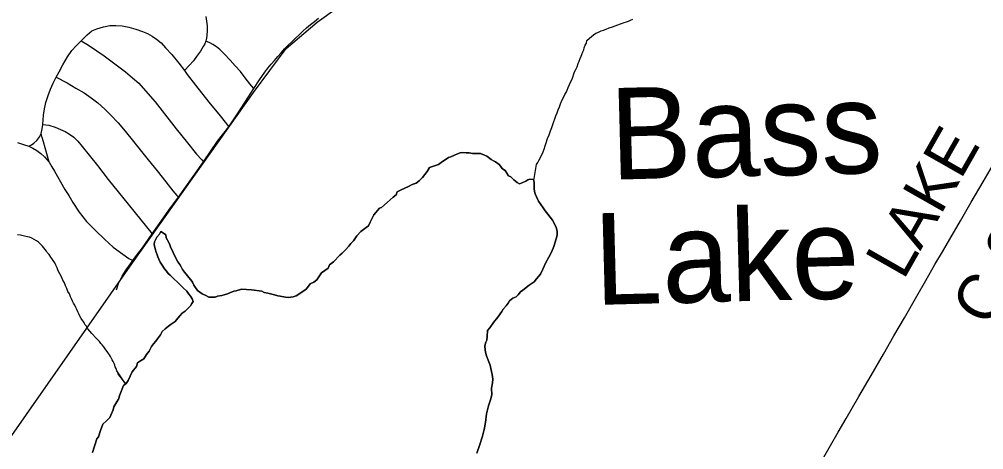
# Model space of a CAD drawing. Extents: x 103424 to 286016, y 38711 to 110967.
# Drawn here: x 137459 to 143819, y 88820 to 91660 of the extents above; entities that cross this region are included whole.
import ezdxf

# ---------------------------------------------------------------- set-up
doc = ezdxf.new("R2010")
doc.units = 0
for name, color, linetype in [('GM_X_County_Road', 7, 'Continuous'), ('GM_X_County_Road_Text', 7, 'Continuous'), ('GM_X_Major_Lake', 7, 'Continuous'), ('GM_X_Major_Lake_Text', 7, 'Continuous'), ('GM_X_Major_River', 7, 'Continuous'), ('GM_X_Minor_River', 7, 'Continuous'), ('GM_X_Rail_Line', 7, 'Continuous'), ('GM_X_Township_Road', 7, 'Continuous')]:
    doc.layers.add(name, color=color, linetype=linetype)

msp = doc.modelspace()

# ---------------------------------------------------------------- linework, layer by layer
at = {"layer": 'GM_X_County_Road'}
msp.add_lwpolyline([(142737.7, 88724.3), (142807.8, 88846.7), (142859.4, 88936.8), (142911.1, 89026.8), (142953.3, 89098.9), (142995.6, 89171), (143076.2, 89310.7), (143156.8, 89450.4), (143226.2, 89570.8), (143295.6, 89691.2), (143378, 89834.2), (143437.6, 89937.6), (143497.2, 90041.1), (143546, 90125), (143594.7, 90209), (143665.5, 90331), (143736.2, 90452.9), (143814.2, 90586.8), (143892.1, 90720.6)], dxfattribs=at)
at = {"layer": 'GM_X_Major_Lake'}
for points in [[(140541.7, 90756), (140527.6, 90764), (140499.3, 90773.9), (140463.1, 90773.7), (140446.9, 90775.6), (140424.7, 90779.6), (140406.6, 90779.5), (140384.4, 90781.4), (140366.3, 90779.2), (140348.2, 90773.1), (140328.1, 90762.9), (140303.9, 90752.7), (140289.8, 90748.6), (140241.6, 90716), (140223.5, 90701.8), (140163.1, 90681.3), (140149.1, 90654.9), (140117, 90616.4), (140097, 90594.1), (140076.9, 90579.9), (140048.7, 90569.6), (140026.6, 90557.4), (139976.3, 90534.9), (139950.1, 90520.7), (139944.2, 90502.5), (139924.1, 90486.2), (139885.9, 90451.7), (139847.8, 90419.2), (139833.7, 90413.1), (139797.6, 90370.5), (139773.6, 90321.9), (139761.6, 90297.6), (139745.5, 90285.4), (139711.3, 90261), (139685.3, 90230.6), (139663.2, 90198.2), (139645.1, 90179.9), (139631.1, 90163.7), (139611, 90139.4), (139589, 90117.1), (139572.9, 90102.9), (139530.7, 90060.3), (139504.6, 90039.9), (139496.7, 90017.7), (139452.4, 89987.2), (139420.4, 89940.6), (139400.3, 89926.3), (139376.1, 89914.1), (139352.1, 89881.7), (139336, 89869.5), (139285.8, 89834.9), (139265.6, 89828.7), (139249.5, 89826.6), (139231.4, 89824.5), (139215.3, 89826.4), (139178.9, 89834.3), (139164.8, 89836.3), (139142.6, 89842.2), (139098.3, 89852), (139074, 89858), (139057.9, 89866), (138991.3, 89875.7), (138924.8, 89879.4), (138888.6, 89869.1), (138874.5, 89867), (138848.3, 89854.7), (138832.2, 89848.6), (138810.1, 89842.4), (138794, 89838.3), (138765.8, 89834.1), (138751.7, 89825.9), (138729.5, 89825.8), (138709.4, 89827.7), (138689.2, 89837.7), (138664.9, 89849.7), (138634.6, 89871.7), (138610.3, 89905.9), (138602.2, 89926), (138590, 89940.1), (138577.9, 89956.2), (138559.7, 89978.3), (138549.5, 89992.3), (138535.3, 90008.4), (138527.2, 90026.5), (138517.1, 90042.6), (138504.9, 90060.7), (138496.8, 90074.8), (138488.7, 90090.9), (138478.5, 90111), (138468.3, 90133.1), (138458.2, 90151.3), (138452.1, 90171.4), (138446, 90187.5), (138435.8, 90203.6), (138427.7, 90217.7), (138425.6, 90237.9), (138409.4, 90249.9), (138393.3, 90259.9), (138383.3, 90241.7), (138365.2, 90223.4), (138359.2, 90209.2)], [(140851.3, 90597.5), (140844.7, 90602.2), (140826.5, 90606.2), (140812.4, 90600.1), (140798.3, 90591.9), (140780.2, 90583.7), (140758.1, 90573.5), (140741.9, 90583.5), (140719.7, 90601.6), (140701.5, 90619.6), (140685.3, 90627.6), (140663, 90661.8), (140644.8, 90673.8), (140622.6, 90701.9), (140600.3, 90720), (140586.2, 90725.9), (140570, 90736), (140541.7, 90756)], [(140476.9, 88798.1), (140492.8, 88848.6), (140512.7, 88909.3), (140524.7, 88953.7), (140532.5, 89000.2), (140540.4, 89056.7), (140552.3, 89109.3), (140566.2, 89149.7), (140574.1, 89182.1), (140574, 89226.4), (140579.9, 89260.8), (140581.8, 89285), (140577.6, 89315.3), (140569.4, 89355.6), (140563.3, 89377.7), (140555.1, 89399.9), (140538.9, 89440.2), (140534.8, 89454.3), (140530.7, 89476.4), (140528.5, 89504.7), (140534.5, 89528.9), (140542.5, 89543.1), (140544.4, 89567.3), (140546.3, 89605.7), (140562.3, 89623.9), (140586.4, 89658.4), (140614.4, 89694.9), (140640.5, 89731.3), (140650.5, 89747.5), (140670.6, 89769.8), (140682.6, 89788.1), (140690.6, 89802.2), (140712.7, 89820.5), (140734.8, 89828.7), (140748.9, 89842.9), (140764.9, 89861.2), (140779, 89873.3), (140821.2, 89905.9), (140853.3, 89928.2), (140869.4, 89948.5), (140895.5, 89978.9), (140911.5, 90011.3), (140931.5, 90055.8), (140951.5, 90090.2), (140969.5, 90122.6), (140983.4, 90161), (140999.4, 90211.6), (141005.3, 90235.8), (141005.2, 90262.1), (140999.1, 90286.2), (140986.9, 90314.4), (140974.7, 90334.5), (140944.3, 90374.7), (140926.1, 90396.8), (140913.9, 90416.9), (140897.7, 90439.1), (140883.5, 90461.2), (140869.3, 90489.4), (140861.1, 90507.5), (140857, 90523.6), (140854.9, 90543.8), (140854.8, 90582.1), (140851.3, 90597.5)], [(138359.2, 90209.2), (138351.2, 90191), (138349.3, 90174.9), (138355.4, 90144.6), (138361.6, 90122.5), (138367.7, 90106.4), (138371.8, 90092.3), (138379.9, 90078.2), (138388, 90058), (138400.2, 90037.9), (138416.4, 90013.8), (138430.6, 89997.7), (138440.7, 89983.7), (138454.9, 89971.6), (138477.1, 89947.5), (138501.4, 89925.5), (138539.9, 89887.3), (138564.1, 89865.3), (138576.3, 89847.2), (138588.4, 89833.1), (138598.6, 89815), (138604.7, 89798.9), (138596.7, 89784.7), (138588.7, 89768.5), (138574.6, 89756.3), (138552.6, 89734), (138532.4, 89721.8), (138518.4, 89703.6), (138504.4, 89687.4), (138486.3, 89667.1), (138460.2, 89648.8), (138442.1, 89634.5), (138422, 89618.3), (138401.9, 89600), (138389.9, 89577.8), (138369.9, 89551.4), (138359.8, 89537.2), (138343.8, 89519), (138329.8, 89500.7), (138315.8, 89470.4), (138297.7, 89448.1), (138279.7, 89419.7), (138257.6, 89405.5), (138237.5, 89393.3), (138231.5, 89369), (138203.4, 89334.6), (138177.5, 89275.9), (138163.4, 89257.6), (138145.4, 89243.4), (138121.4, 89182.8), (138113.5, 89154.5), (138101.4, 89136.2), (138083.4, 89103.8), (138077.5, 89083.6), (138063.5, 89047.2), (138055.5, 89033.1), (138033.4, 89010.7), (138009.3, 88988.4), (137995.4, 88946), (137981.4, 88905.5), (137969.4, 88891.3), (137941.5, 88802.4)]]:
    msp.add_lwpolyline(points, dxfattribs=at)
at = {"layer": 'GM_X_Major_River'}
for points in [[(140851.3, 90597.5), (140869.9, 90702.3), (140877.8, 90714.6), (140885.6, 90728.9), (140893.4, 90743.2), (140901.2, 90759.5), (140909, 90773.7), (140912.8, 90785.9), (140920.6, 90804.3), (140926.2, 90824.6), (140933.9, 90844.9), (140941.5, 90873.3), (140953.2, 90897.8), (140962.8, 90924.2), (140970.5, 90946.6), (140978.2, 90966.9), (140983.9, 90985.2), (140991.6, 91003.5), (140997.3, 91023.9), (141005.1, 91042.2), (141012.8, 91062.5), (141020.5, 91082.9), (141028.2, 91103.2), (141039.8, 91129.7), (141049.6, 91148), (141057.4, 91164.3), (141065.2, 91176.6), (141071, 91192.9), (141078.7, 91211.2), (141086.5, 91229.5), (141096.2, 91249.9), (141104, 91266.2), (141121.3, 91313), (141129.1, 91329.3), (141136.8, 91347.6), (141144.5, 91367.9), (141150.3, 91384.2), (141158, 91402.5), (141163.8, 91416.8), (141169.6, 91429), (141175.4, 91445.3), (141181.2, 91459.5), (141185, 91471.7), (141190.7, 91490), (141198.6, 91502.3), (141202.3, 91520.5), (141218.2, 91534.9), (141232.1, 91547.3), (141246, 91557.7), (141262, 91568.1), (141274, 91572.3), (141296, 91584.8), (141312.1, 91589.2), (141328.1, 91595.5), (141348.1, 91604), (141370.2, 91610.4), (141388.2, 91616.8), (141406.3, 91623.2), (141424.3, 91629.6), (141436.4, 91633.8), (141448.4, 91638.1), (141462.4, 91644.4), (141476.5, 91648.7), (141490.5, 91655), (141504.5, 91661.3)], [(138359.2, 90209.2), (138365.2, 90223.4), (138383.3, 90241.7), (138393.3, 90259.9), (138409.4, 90249.9), (138425.6, 90237.9), (138427.7, 90217.7), (138435.8, 90203.6), (138446, 90187.5), (138452.1, 90171.4), (138458.2, 90151.3), (138468.3, 90133.1), (138478.5, 90111), (138488.7, 90090.9), (138496.8, 90074.8), (138504.9, 90060.7), (138517.1, 90042.6), (138527.2, 90026.5), (138535.3, 90008.4), (138549.5, 89992.3), (138559.7, 89978.3), (138577.9, 89956.2), (138590, 89940.1), (138602.2, 89926), (138610.3, 89905.9), (138634.6, 89871.7), (138664.9, 89849.7), (138689.2, 89837.7), (138709.4, 89827.7), (138729.5, 89825.8), (138751.7, 89825.9), (138765.8, 89834.1), (138794, 89838.3), (138810.1, 89842.4), (138832.2, 89848.6), (138848.3, 89854.7), (138874.5, 89867), (138888.6, 89869.1), (138924.8, 89879.4), (138991.3, 89875.7), (139057.9, 89866), (139074, 89858), (139098.3, 89852), (139142.6, 89842.2), (139164.8, 89836.3), (139178.9, 89834.3), (139215.3, 89826.4), (139231.4, 89824.5), (139249.5, 89826.6), (139265.6, 89828.7), (139285.8, 89834.9), (139336, 89869.5), (139352.1, 89881.7), (139376.1, 89914.1), (139400.3, 89926.3), (139420.4, 89940.6), (139452.4, 89987.2), (139496.7, 90017.7), (139504.6, 90039.9), (139530.7, 90060.3), (139572.9, 90102.9), (139589, 90117.1), (139611, 90139.4), (139631.1, 90163.7), (139645.1, 90179.9), (139663.2, 90198.2), (139685.3, 90230.6), (139711.3, 90261), (139745.5, 90285.4), (139761.6, 90297.6), (139773.6, 90321.9), (139797.6, 90370.5), (139833.7, 90413.1), (139847.8, 90419.2), (139885.9, 90451.7), (139924.1, 90486.2), (139944.2, 90502.5), (139950.1, 90520.7), (139976.3, 90534.9), (140026.6, 90557.4), (140048.7, 90569.6), (140076.9, 90579.9), (140097, 90594.1), (140117, 90616.4), (140149.1, 90654.9), (140163.1, 90681.3), (140223.5, 90701.8), (140241.6, 90716), (140289.8, 90748.6), (140303.9, 90752.7), (140328.1, 90762.9), (140348.2, 90773.1), (140366.3, 90779.2), (140384.4, 90781.4), (140406.6, 90779.5), (140424.7, 90779.6), (140446.9, 90775.6), (140463.1, 90773.7), (140499.3, 90773.9), (140527.6, 90764), (140541.7, 90756)], [(140541.7, 90756), (140570, 90736), (140586.2, 90725.9), (140600.3, 90720), (140622.6, 90701.9), (140644.8, 90673.8), (140663, 90661.8), (140685.3, 90627.6), (140701.5, 90619.6), (140719.7, 90601.6), (140741.9, 90583.5), (140758.1, 90573.5), (140780.2, 90583.7), (140798.3, 90591.9), (140812.4, 90600.1), (140826.5, 90606.2), (140844.7, 90602.2), (140851.3, 90597.5)], [(140851.3, 90597.5), (140854.8, 90582.1), (140854.9, 90543.8), (140857, 90523.6), (140861.1, 90507.5), (140869.3, 90489.4), (140883.5, 90461.2), (140897.7, 90439.1), (140913.9, 90416.9), (140926.1, 90396.8), (140944.3, 90374.7), (140974.7, 90334.5), (140986.9, 90314.4), (140999.1, 90286.2), (141005.2, 90262.1), (141005.3, 90235.8), (140999.4, 90211.6), (140983.4, 90161), (140969.5, 90122.6), (140951.5, 90090.2), (140931.5, 90055.8), (140911.5, 90011.3), (140895.5, 89978.9), (140869.4, 89948.5), (140853.3, 89928.2), (140821.2, 89905.9), (140779, 89873.3), (140764.9, 89861.2), (140748.9, 89842.9), (140734.8, 89828.7), (140712.7, 89820.5), (140690.6, 89802.2), (140682.6, 89788.1), (140670.6, 89769.8), (140650.5, 89747.5), (140640.5, 89731.3), (140614.4, 89694.9), (140586.4, 89658.4), (140562.3, 89623.9), (140546.3, 89605.7), (140544.4, 89567.3), (140542.5, 89543.1), (140534.5, 89528.9), (140528.5, 89504.7), (140530.7, 89476.4), (140534.8, 89454.3), (140538.9, 89440.2), (140555.1, 89399.9), (140563.3, 89377.7), (140569.4, 89355.6), (140577.6, 89315.3), (140581.8, 89285), (140579.9, 89260.8), (140574, 89226.4), (140574.1, 89182.1), (140566.2, 89149.7), (140552.3, 89109.3), (140540.4, 89056.7), (140532.5, 89000.2), (140524.7, 88953.7), (140512.7, 88909.3), (140492.8, 88848.6), (140476.9, 88798.1)], [(137941.5, 88802.4), (137969.4, 88891.3), (137981.4, 88905.5), (137995.4, 88946), (138009.3, 88988.4), (138033.4, 89010.7), (138055.5, 89033.1), (138063.5, 89047.2), (138077.5, 89083.6), (138083.4, 89103.8), (138101.4, 89136.2), (138113.5, 89154.5), (138121.4, 89182.8), (138145.4, 89243.4), (138163.4, 89257.6), (138177.5, 89275.9), (138203.4, 89334.6), (138231.5, 89369), (138237.5, 89393.3), (138257.6, 89405.5), (138279.7, 89419.7), (138297.7, 89448.1), (138315.8, 89470.4), (138329.8, 89500.7), (138343.8, 89519), (138359.8, 89537.2), (138369.9, 89551.4), (138389.9, 89577.8), (138401.9, 89600), (138422, 89618.3), (138442.1, 89634.5), (138460.2, 89648.8), (138486.3, 89667.1), (138504.4, 89687.4), (138518.4, 89703.6), (138532.4, 89721.8), (138552.6, 89734), (138574.6, 89756.3), (138588.7, 89768.5), (138596.7, 89784.7), (138604.7, 89798.9), (138598.6, 89815), (138588.4, 89833.1), (138576.3, 89847.2), (138564.1, 89865.3), (138539.9, 89887.3), (138501.4, 89925.5), (138477.1, 89947.5), (138454.9, 89971.6), (138440.7, 89983.7), (138430.6, 89997.7), (138416.4, 90013.8), (138400.2, 90037.9), (138388, 90058), (138379.9, 90078.2), (138371.8, 90092.3), (138367.7, 90106.4), (138361.6, 90122.5), (138355.4, 90144.6), (138349.3, 90174.9), (138351.2, 90191), (138359.2, 90209.2)]]:
    msp.add_lwpolyline(points, dxfattribs=at)
at = {"layer": 'GM_X_Minor_River'}
msp.add_lwpolyline([(138106, 89323.2), (138158.6, 89253.9), (138101.6, 89341.3), (138097.3, 89355.4), (138091.1, 89367.4), (138088.9, 89377.5), (138084.6, 89389.5), (138078.4, 89401.5), (138072.1, 89413.5), (138065.8, 89425.5), (138059.6, 89435.5), (138053.3, 89445.5), (138047.1, 89455.5), (138038.8, 89467.5), (138030.5, 89479.5), (138016.1, 89499.4), (138005.8, 89511.3), (137997.5, 89521.3), (137987.2, 89533.2), (137976.9, 89545.2), (137966.6, 89557.1), (137937.8, 89586.9), (137923.4, 89602.8), (137911, 89618.7), (137900.6, 89636.7), (137892.3, 89646.7), (137886.1, 89658.7), (137877.8, 89670.7), (137867.4, 89686.6), (137859.1, 89700.6), (137850.7, 89716.6), (137844.4, 89730.7), (137838.1, 89744.7), (137831.8, 89758.7), (137825.5, 89772.8), (137817.2, 89786.8), (137808.9, 89800.7), (137802.6, 89814.8), (137796.3, 89828.8), (137789.8, 89848.9), (137779.5, 89864.9), (137773.1, 89882.9), (137764.7, 89901), (137756.3, 89921), (137745.8, 89939), (137737.4, 89961.1), (137726.9, 89981.1), (137716.5, 90001.1), (137708.1, 90019.2), (137699.7, 90037.2), (137693.3, 90053.2), (137683, 90069.2), (137674.7, 90081.2), (137666.4, 90091.1), (137656.1, 90107.1), (137643.7, 90121), (137637.5, 90131), (137629.2, 90141), (137620.9, 90153), (137612.7, 90162.9), (137598.3, 90176.8), (137586, 90188.7), (137571.7, 90198.5), (137541.1, 90216.2), (137526.9, 90222), (137512.7, 90225.8), (137494.4, 90229.5), (137468.1, 90235.1), (137447.9, 90238.7)], dxfattribs=at)
at = {"layer": 'GM_X_Rail_Line'}
msp.add_lwpolyline([(133875.3, 84761), (134206.1, 85023.5), (134695.7, 85421.3), (135168.4, 85804.7), (135472.6, 86146.8), (135770.9, 86563.5), (136107.4, 87051.7), (138204.8, 90053), (139003.6, 91176.8), (139218.1, 91468.2), (139423.2, 91640.3), (139671.2, 91822), (140345.3, 92305.3), (142112.2, 93585.6), (142557.7, 93916.9), (142922.5, 94241.9), (143182.7, 94627.5), (143325.5, 94997.6), (143391, 95277.5), (143535.3, 96306.5), (143604.3, 97220.4), (143676.2, 97697.4)], dxfattribs=at)
at = {"layer": 'GM_X_Township_Road'}
for points in [[(138208.1, 90067.8), (138232.9, 90102.1), (138272.1, 90152.9), (138336.2, 90244.4), (138410.4, 90350.7), (138445.1, 90400.2), (138508.5, 90487.4), (138557.6, 90554.7), (138606.7, 90622), (138674.2, 90719.5), (138720.6, 90788.2), (138767, 90856.9), (138839.8, 90951.2), (138897.3, 91037.2), (138946.8, 91111.4), (139006.2, 91202.5), (139043.9, 91260.2), (139078, 91310.5), (139099, 91337.4), (139119.9, 91363.5), (139141.3, 91389.3), (139163.3, 91414.7), (139185.7, 91439.8), (139208.3, 91464.4), (139231.8, 91488.6), (139255.2, 91512.4), (139279.4, 91535.8), (139303.8, 91558.8), (139328.7, 91581.4), (139353.9, 91603.5), (139379.6, 91625.2), (139405.6, 91646.3), (139431.7, 91667.1)], [(138688.6, 91678), (138694.4, 91647.4), (138697.4, 91616.8), (138698.7, 91584.5), (138696.8, 91556), (138693.6, 91535.1), (138689.2, 91514.9), (138682.2, 91498.4), (138672.5, 91479.9), (138653.7, 91450.3), (138628.7, 91414.8), (138607.3, 91386.3), (138578.7, 91355.2), (138548.9, 91323.3)], [(137521.1, 90823.1), (137539.6, 90832.1), (137555.5, 90842), (137575.4, 90861.2), (137594.7, 90887.1), (137604.2, 90907.1), (137610.8, 90938.4), (137615.1, 90966.9), (137619.8, 91027.2), (137625.8, 91068.7), (137634.9, 91111.9), (137648.8, 91156.3), (137665.4, 91198.7), (137683.5, 91239.4), (137703.2, 91277.6), (137721.1, 91314.1), (137747.2, 91360.3), (137777.2, 91413.5), (137804.6, 91453.9), (137833.1, 91485.1), (137868.2, 91518.9), (137906.7, 91556.7), (137936.5, 91583.2), (137970.9, 91598.4), (138014.7, 91611), (138056.4, 91618.3), (138096.2, 91620.3), (138138, 91616.3), (138180.4, 91608.3), (138227.4, 91595.8), (138271.9, 91579.9), (138305, 91566.6), (138335.5, 91549.4), (138363.3, 91530.1), (138393.8, 91504.3), (138424.3, 91471.8), (138464.1, 91428.1), (138510.5, 91370.4), (138548.9, 91323.3), (138566.8, 91296.8), (138620.5, 91225.2), (138709.3, 91113.2), (138782.9, 91023.8), (138839.8, 90951.2)], [(137868.2, 91518.9), (137914.6, 91489.7), (137969.6, 91451.9), (138018.7, 91418.8), (138088.9, 91367.1), (138158.9, 91314.3), (138206.3, 91275), (138248, 91237.8), (138292.4, 91188.8), (138354.7, 91115.9), (138417, 91036.3), (138494.3, 90937.7), (138568.9, 90845.4), (138628.3, 90771.2), (138663.1, 90731.8), (138674.2, 90719.5)], [(139006.2, 91202.5), (138980.3, 91234.8), (138949.3, 91275), (138917, 91314.9), (138883.5, 91352.2), (138849.9, 91390.2), (138812.6, 91430.7), (138781.6, 91461.1), (138759.4, 91478.8), (138735.4, 91493.3), (138715.2, 91504), (138689.2, 91514.9)], [(137703.2, 91277.6), (137773.7, 91241.1), (137832.8, 91206.7), (137885.9, 91175.7), (137932.7, 91141.3), (137976.9, 91108.6), (138023.8, 91067.1), (138060.9, 91030.8), (138111.2, 90976), (138158.1, 90921.3), (138212, 90853.2), (138309.2, 90733.9), (138367.5, 90660.9), (138425.9, 90588), (138470.9, 90529.2), (138497.4, 90496.8), (138508.5, 90487.4)], [(137615.1, 90966.9), (137653.6, 90960.7), (137696.1, 90948.1), (137729.9, 90933.5), (137761.7, 90918.9), (137790.9, 90902.3), (137818, 90882.4), (137844.5, 90855.9), (137873.1, 90821.6), (137920.9, 90764.3), (137974.9, 90694.9), (138045.6, 90603.6), (138111, 90522.4), (138176.4, 90441.2), (138260.7, 90338), (138336.2, 90244.4)], [(137655, 90718.2), (137629.3, 90811.5), (137618.9, 90851.1), (137610.8, 90880), (137604.2, 90907.1)], [(137447.1, 90846.8), (137486, 90833.5), (137521.1, 90823.1), (137548.2, 90810.8), (137574.3, 90794.6), (137602, 90774.4), (137625.5, 90752.4), (137655, 90718.2), (137674.4, 90687.4), (137691, 90658.1), (137730.3, 90588.4), (137758.9, 90536.8), (137785.2, 90497.2), (137812.3, 90452.4), (137854.7, 90387.6), (137903, 90326.3), (137964.3, 90263.9), (138020.9, 90209.7), (138078.6, 90156.7), (138141, 90109.5), (138182.5, 90082.6), (138208.1, 90067.8)], [(138101.1, 89875.6), (138114.3, 89916.8), (138136.6, 89965.8), (138163.6, 90006.8), (138192.5, 90046.7), (138208.1, 90067.8)]]:
    msp.add_lwpolyline(points, dxfattribs=at)

# ---------------------------------------------------------------- texts
at = {"layer": 'GM_X_County_Road_Text'}
for s, rotation, p in [('LAKE', 60.34711, (143289.2, 89933.7)), ('C-23', 60.25515, (143856.8, 89620.9))]:
    msp.add_text(s, height=301.87, rotation=rotation, dxfattribs=at).set_placement(p)
at = {"layer": 'GM_X_Major_Lake_Text'}
for s, height, rotation, p in [('Bass', 604.15, 1.49831, (141360.3, 90601.4)), ('Lake', 604.14, 1.49788, (141254.8, 89775))]:
    msp.add_text(s, height=height, rotation=rotation, dxfattribs=at).set_placement(p)

doc.saveas('drawing.dxf')
